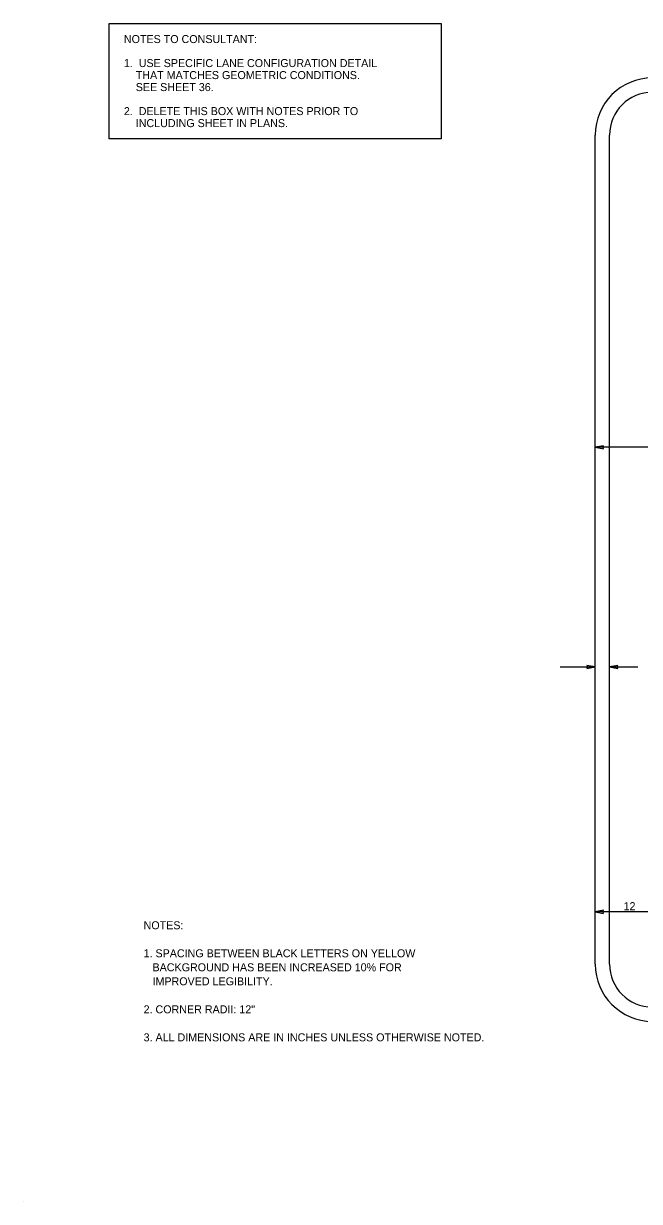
# Model space of a CAD drawing. Extents: x 319706 to 320019, y 1621790 to 1621996.
# Drawn here: x 319705.9 to 319813.6, y 1621790 to 1621996 of the extents above; entities that cross this region are included whole.
import ezdxf

# ---------------------------------------------------------------- set-up
doc = ezdxf.new("R2010")
doc.units = 0
for name, color, linetype in [('1', 7, 'Continuous'), ('48', 7, 'Continuous'), ('52', 7, 'Continuous'), ('AdhocPoint_dp', 7, 'Continuous'), ('TextAlert', 7, 'Continuous'), ('TextNotes', 7, 'Continuous')]:
    doc.layers.add(name, color=color, linetype=linetype)

msp = doc.modelspace()

# ---------------------------------------------------------------- linework, layer by layer
at = {"layer": '1'}
for p, q in [((319805.88, 1621831.54), (319805.88, 1621976.54)), ((319808.38, 1621831.54), (319808.38, 1621976.54))]:
    msp.add_line(p, q, dxfattribs=at)
for centre, radius, start, end in [((319815.88, 1621976.54), 10, 90, 180), ((319815.88, 1621976.54), 7.5, 90, 180), ((319815.88, 1621831.54), 10, 180, 270), ((319815.88, 1621831.54), 7.5, 180, 270)]:
    msp.add_arc(centre, radius, start, end, dxfattribs=at)
at = {"layer": '48'}
for p, q in [((319830.47, 1621921.96), (319805.88, 1621921.96)), ((319799.75, 1621883.55), (319805.88, 1621883.55)), ((319808.38, 1621883.55), (319813.32, 1621883.55)), ((319815.88, 1621840.71), (319805.88, 1621840.71))]:
    msp.add_line(p, q, dxfattribs=at)
at = {"layer": '52'}
for p, q in [((319807.31, 1621922.21), (319805.86, 1621921.94)), ((319805.86, 1621921.94), (319807.31, 1621921.66)), ((319807.2, 1621921.94), (319807.31, 1621922.21)), ((319807.31, 1621921.66), (319807.2, 1621921.94)), ((319805.86, 1621883.52), (319804.41, 1621883.8)), ((319804.41, 1621883.8), (319804.52, 1621883.52)), ((319804.52, 1621883.52), (319804.41, 1621883.25)), ((319804.41, 1621883.25), (319805.86, 1621883.52)), ((319809.81, 1621883.79), (319808.36, 1621883.52)), ((319808.36, 1621883.52), (319809.81, 1621883.24)), ((319809.7, 1621883.52), (319809.81, 1621883.79)), ((319809.81, 1621883.24), (319809.7, 1621883.52)), ((319807.31, 1621840.97), (319805.86, 1621840.7)), ((319805.86, 1621840.7), (319807.31, 1621840.42)), ((319807.2, 1621840.7), (319807.31, 1621840.97)), ((319807.31, 1621840.42), (319807.2, 1621840.7))]:
    msp.add_line(p, q, dxfattribs=at)
at = {"layer": 'AdhocPoint_dp'}
msp.add_line((319705.88, 1621790.04), (319705.88, 1621790.04), dxfattribs=at)
at = {"layer": 'TextAlert'}
msp.add_lwpolyline([(319720.88, 1621996.04), (319778.91, 1621996.04), (319778.91, 1621975.87), (319720.88, 1621975.87)], close=True, dxfattribs=at)

# ---------------------------------------------------------------- texts
at = {"layer": '48'}
msp.add_text('12', height=1.4, dxfattribs=at).set_placement((319810.84, 1621840.98))
at = {"layer": 'TextAlert'}
for s, p in [('NOTES TO CONSULTANT:', (319723.43, 1621992.63)), ('1.  USE SPECIFIC LANE CONFIGURATION DETAIL', (319723.43, 1621988.43)), ('    THAT MATCHES GEOMETRIC CONDITIONS. ', (319723.43, 1621986.33)), ('    SEE SHEET 36.', (319723.43, 1621984.23)), ('2.  DELETE THIS BOX WITH NOTES PRIOR TO ', (319723.43, 1621980.03)), ('    INCLUDING SHEET IN PLANS.', (319723.43, 1621977.93))]:
    msp.add_text(s, height=1.4, dxfattribs=at).set_placement(p)
at = {"layer": 'TextNotes'}
for s, p in [('NOTES:', (319726.88, 1621837.64)), ('1. SPACING BETWEEN BLACK LETTERS ON YELLOW', (319726.88, 1621832.74)), ('   BACKGROUND HAS BEEN INCREASED 10% FOR', (319726.88, 1621830.29)), ('   IMPROVED LEGIBILITY.', (319726.88, 1621827.84)), ('2. CORNER RADII: 12"', (319726.88, 1621822.94)), ('3. ALL DIMENSIONS ARE IN INCHES UNLESS OTHERWISE NOTED.', (319726.88, 1621818.04))]:
    msp.add_text(s, height=1.4, dxfattribs=at).set_placement(p)

doc.saveas('drawing.dxf')
